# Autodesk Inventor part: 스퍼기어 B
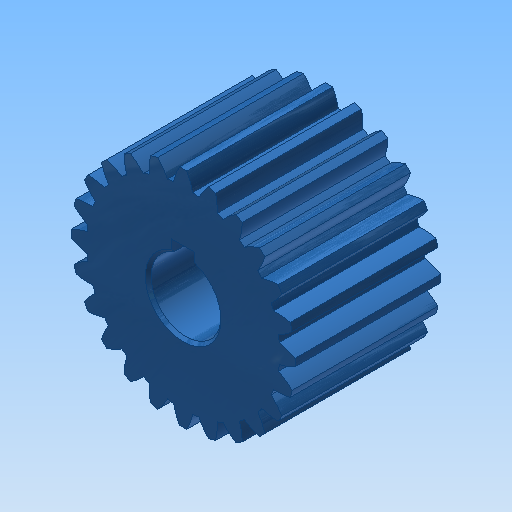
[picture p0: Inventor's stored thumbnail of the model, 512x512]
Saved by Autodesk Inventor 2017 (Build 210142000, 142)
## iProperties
Created: 2020-04
Part Number: 스퍼기어 B
Material: 강철, 연강
Document SubType Name: Modeling
Designer: mduedu
Categories: <?xml version="1.0" encoding="UTF-16"?> <MemberInstance><Categories><FamilyTemplate><FamilyTemplateParameter ValueType="xs:double" Id="1" ObjectReferenceKey="da
Density: 7.86 g/cm^3
Mass: 175.416 g
Surface Area: 76.8935 cm^2
Volume: 22.3176 cm^3
Appearance: 청록색
CustomPartVersion: 1
Author: mduedu
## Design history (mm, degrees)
sketch "Sketch1"
  geometry: C1 r 19.2 at (0, 0)
  constraints: 1 centre point
  dimensions: "d0" = 38.4 diameter of C1 (= da_da)
extrude "Extrusion1" new body sketch "Sketch1" distance "d1" = 25 (= da_b); taper "d2" = 0 deg
workplane "Work Plane2"
sketch "Sketch2"
  geometry: C1 r 19.2 at (0, 0) reference; C2 r 18 at (0, 0)
  constraints: 1 centre point, 1 coincident
  dimensions: "d3" = 36 diameter of C2 (= da_dw)
feature "피치 지름" sketch "Sketch2" dims "d4" = 10, "d5" = 0
workplane "Work Plane8"
workplane "Work Plane9"
feature "스퍼 기어" dims "da_b" = 25, "da_d" = 36, "da_aw" = 45, "da_da" = 38.4, "da_df" = 33.129, "da_dw" = 36, angle "da_beta" = 0 deg, "da_lefttooth" = 0, "da_righttooth" = 0
sketch "스케치3"
  geometry: L1 (-2, 5.657)-(2, 5.657); L2 (2, 5.657)-(2, 7.8); L3 (2, 7.8)-(-2, 7.8); L4 (-2, 7.8)-(-2, 5.657); A1 r 6 centre (0, 0) between (-2, 5.657) and (2, 5.657); 1 further point
  constraints: 8 end point, 2 parallel, 2 point on circle, 1 centre point, 1 coincident, 1 horizontal, 1 perpendicular
  dimensions: "d49" = 12 diameter of A1; "d51" = 4 distance of L2.end L3.end; "d52" = 13.8 dimension on A1 L3
extrude "돌출2" cut sketch "스케치3" stored distance "d53" = 10; taper "d54" = 0 deg
chamfer "모따기1" distance "d55" = 0.5; stored, may be unused: second distance "d56" = 2, angle "d57" = 45 deg
body "Solid1"
body "Srf1"
other parameters: "d16" = 45 (= da_aw), "d17" = 0, "d34" = 7.5 deg (computed from da_z), "d39" = 0, "d41" = 0, "d43" = 45 (= da_aw), "d46" = 45 (= da_aw), "d47" = 0, "d48" = 0
